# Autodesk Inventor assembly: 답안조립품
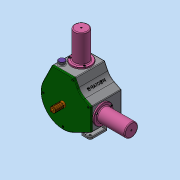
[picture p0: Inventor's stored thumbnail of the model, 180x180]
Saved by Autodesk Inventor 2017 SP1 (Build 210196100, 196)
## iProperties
Part Number: 답안조립품
Material: 일반
Document SubType Name: Assembly
Designer: MRC
Author: MRC
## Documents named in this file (13)
- C:\Users\MRC\Desktop\611109V1005\답안조립품.iam
- C:\Users\MRC\Desktop\611109V1005\본체.ipt
- C:\Users\MRC\Desktop\611109V1005\너트 M3.ipt
- C:\Users\MRC\Desktop\611109V1005\베어링 20 x 37 x 9.ipt
- C:\Users\MRC\Desktop\611109V1005\볼트 M3 x 12.ipt
- C:\Users\MRC\Desktop\611109V1005\실린더.ipt
- C:\Users\MRC\Desktop\611109V1005\앞커버.ipt
- C:\Users\MRC\Desktop\611109V1005\축.ipt
- C:\Users\MRC\Desktop\611109V1005\측정게이지.ipt
- C:\Users\MRC\Desktop\611109V1005\커넥팅로드 캡.ipt
- C:\Users\MRC\Desktop\611109V1005\커넥팅로드.ipt
- C:\Users\MRC\Desktop\611109V1005\피스톤 핀.ipt
- C:\Users\MRC\Desktop\611109V1005\피스톤.ipt
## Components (4 placed, 2 different names)
1. 피스톤 핀:1
2. 피스톤:1
3. 피스톤 핀:2 — 플러쉬:1
4. 피스톤:2 — 플러쉬:1
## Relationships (1: Flush 1)
- 플러쉬:1 [Flush]: 피스톤 핀:2 ↔ 피스톤:2
## Named parameters: d24_d22 = 0
